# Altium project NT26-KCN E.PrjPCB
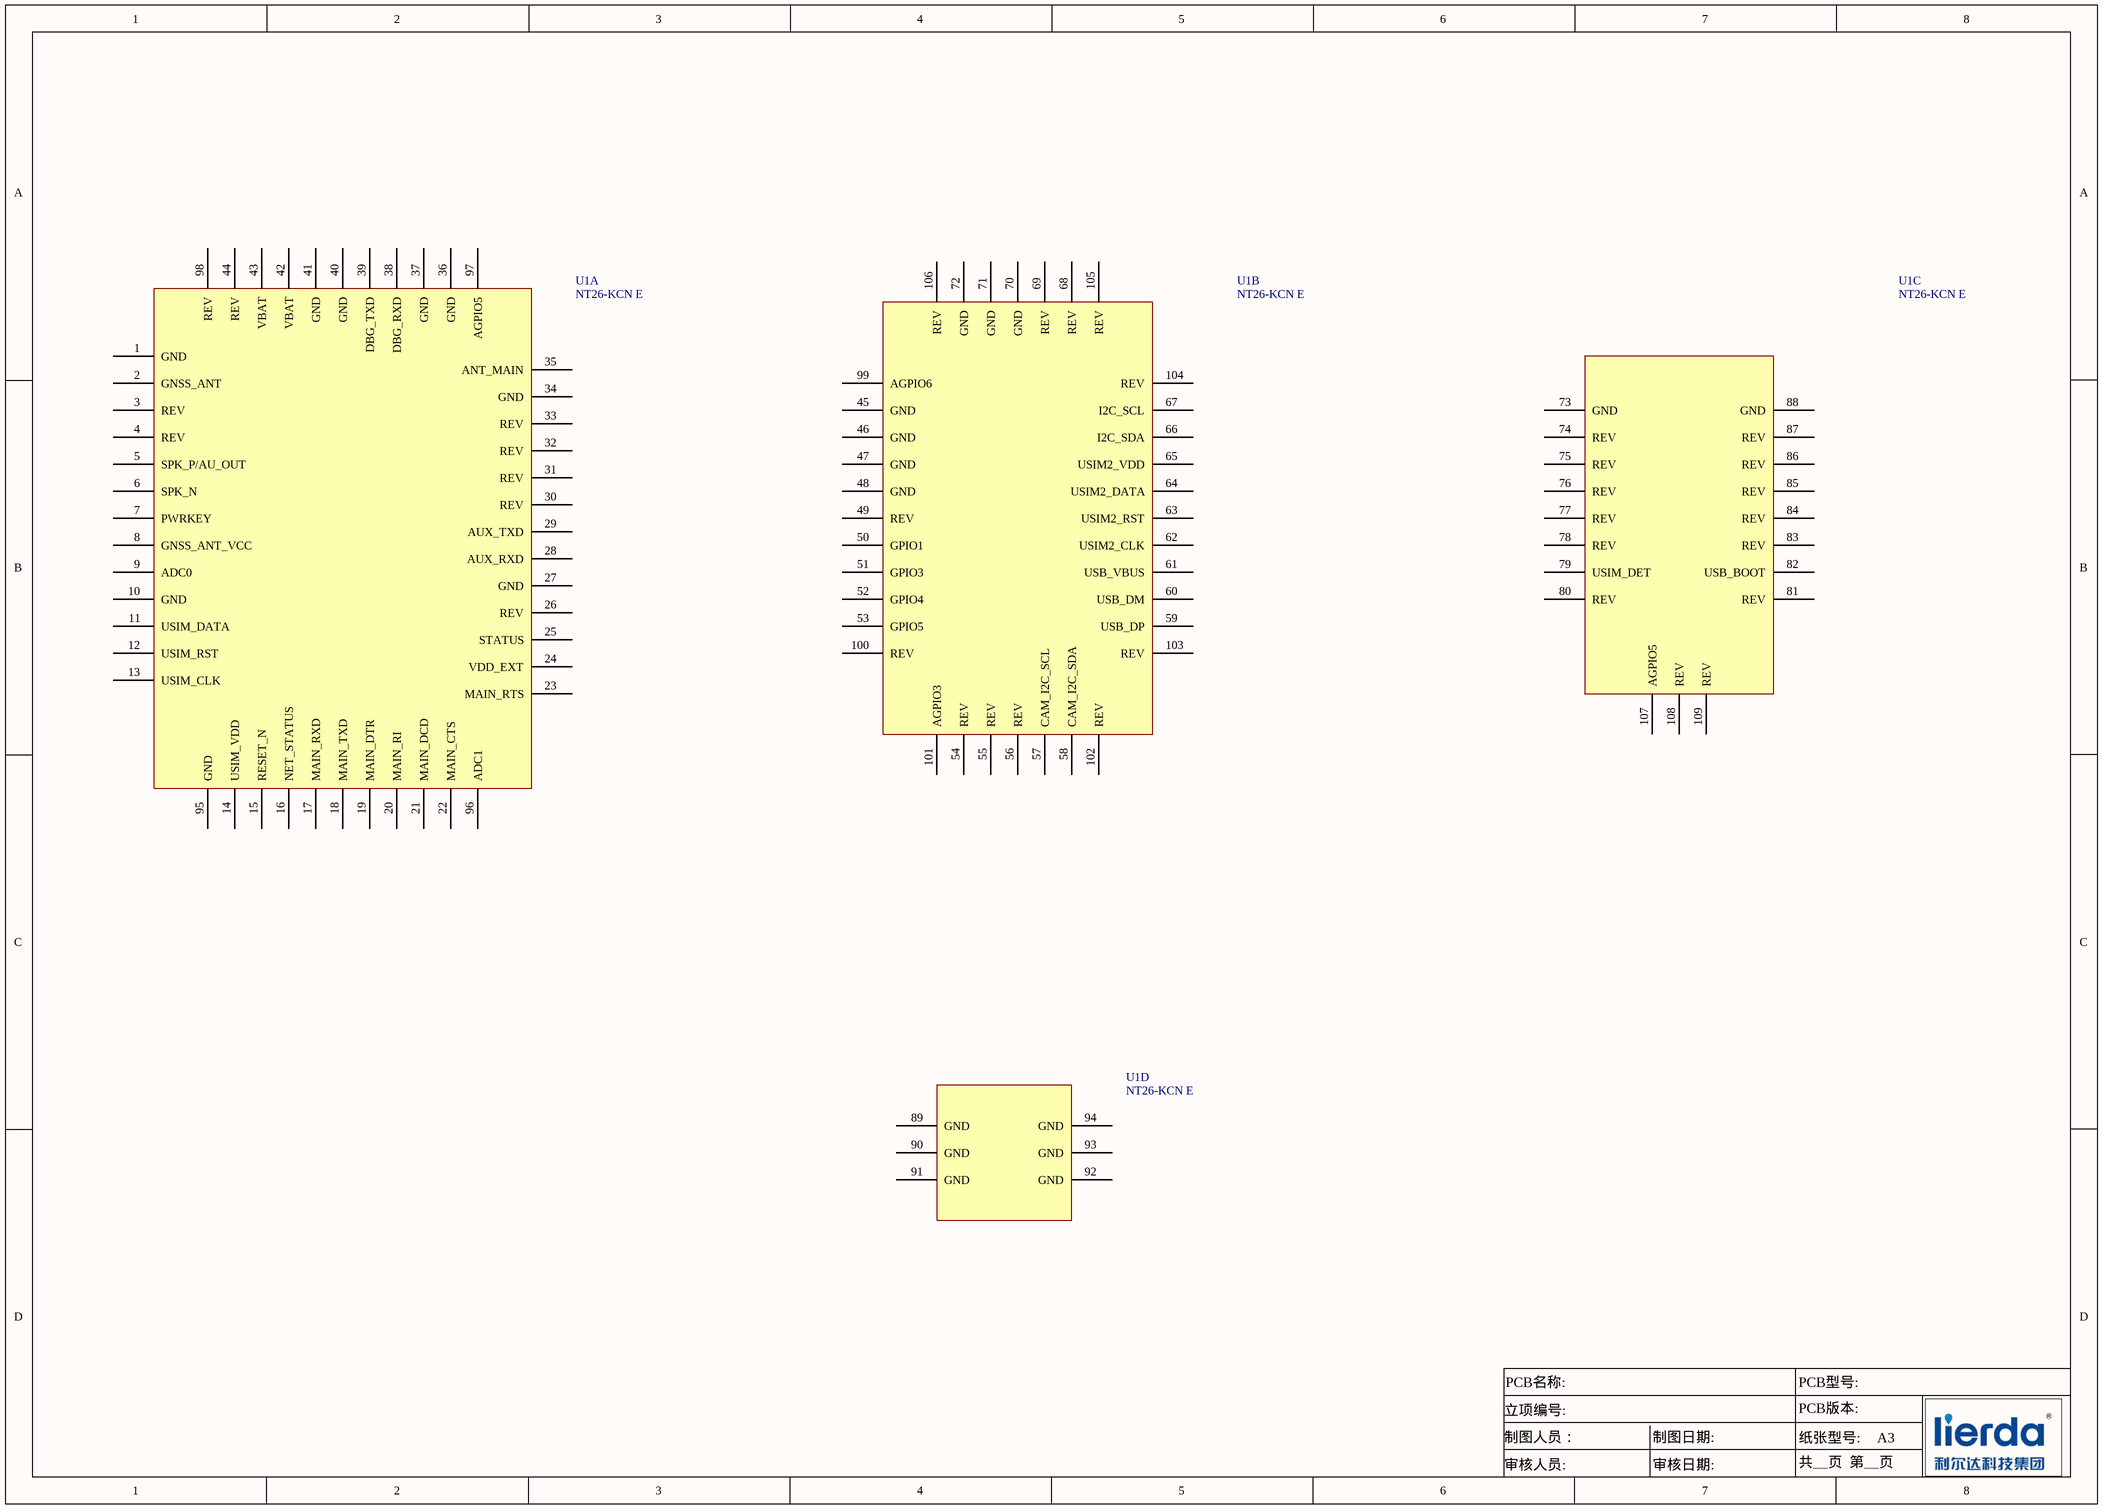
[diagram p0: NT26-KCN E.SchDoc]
1 sheet, 1 parts. Net scope: global (net labels, ports and power ports of the same name join across sheets).
Board file: NT26-KCN E.PcbDoc

## Sheet NT26-KCN E.SchDoc
size A3

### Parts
U1  NT26-KCN E  [NT26-KCN E]  (parts A,B,C,D of 4)

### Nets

Not connected (* = marked no-connect by the designer): U1 1(GND) 2(GNSS_ANT) 3(REV) 4(REV) 5(SPK_P/AU_OUT) 6(SPK_N) 7(PWRKEY) 8(GNSS_ANT_VCC) 9(ADC0) 10(GND) 11(USIM_DATA) 12(USIM_RST) 13(USIM_CLK) 14(USIM_VDD) 15(RESET_N) 16(NET_STATUS) 17(MAIN_RXD) 18(MAIN_TXD) 19(MAIN_DTR) 20(MAIN_RI) 21(MAIN_DCD) 22(MAIN_CTS) 23(MAIN_RTS) 24(VDD_EXT) 25(STATUS) 26(REV) 27(GND) 28(AUX_RXD) 29(AUX_TXD) 30(REV) 31(REV) 32(REV) 33(REV) 34(GND) 35(ANT_MAIN) 36(GND) 37(GND) 38(DBG_RXD) 39(DBG_TXD) 40(GND) 41(GND) 42(VBAT) 43(VBAT) 44(REV) 45(GND) 46(GND) 47(GND) 48(GND) 49(REV) 50(GPIO1) 51(GPIO3) 52(GPIO4) 53(GPIO5) 54(REV) 55(REV) 56(REV) 57(CAM_I2C_SCL) 58(CAM_I2C_SDA) 59(USB_DP) 60(USB_DM) 61(USB_VBUS) 62(USIM2_CLK) 63(USIM2_RST) 64(USIM2_DATA) 65(USIM2_VDD) 66(I2C_SDA) 67(I2C_SCL) 68(REV) 69(REV) 70(GND) 71(GND) 72(GND) 73(GND) 74(REV) 75(REV) 76(REV) 77(REV) 78(REV) 79(USIM_DET) 80(REV) 81(REV) 82(USB_BOOT) 83(REV) 84(REV) 85(REV) 86(REV) 87(REV) 88(GND) 89(GND) 90(GND) 91(GND) 92(GND) 93(GND) 94(GND) 95(GND) 96(ADC1) 97(AGPIO5) 98(REV) 99(AGPIO6) 100(REV) 101(AGPIO3) 102(REV) 103(REV) 104(REV) 105(REV) 106(REV) 107(AGPIO5) 108(REV) 109(REV)

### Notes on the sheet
- PCB名称:
- PCB型号:
- 制图人员：
- 立项编号:
- 制图日期:
- PCB版本:
- 纸张型号:
- A3
- 审核人员:
- 审核日期:
- 共__页  第__页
